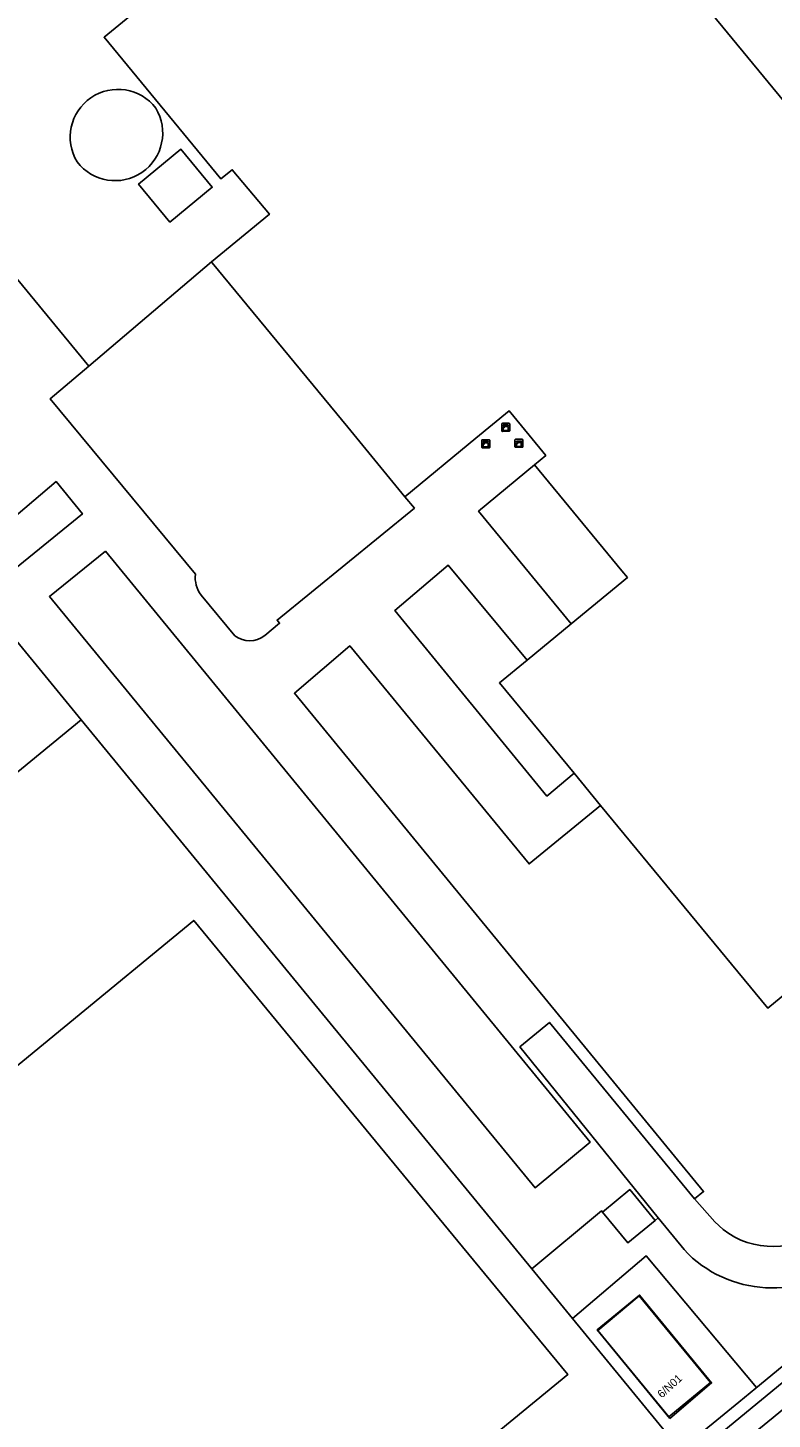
# Model space of a CAD drawing. Extents: x 156141 to 158132, y 385651 to 388333.
# Drawn here: x 157145.1 to 157238.1, y 386478.5 to 386652.3 of the extents above; entities that cross this region are included whole.
import ezdxf

# ---------------------------------------------------------------- set-up
doc = ezdxf.new("R2010")
doc.units = 0
for name, color, linetype in [('IMGEO_Berm_groen', 7, 'Continuous'), ('IMGEO_Erf', 7, 'Continuous'), ('IMGEO_Fietspad_gesloten', 7, 'Continuous'), ('IMGEO_Hek', 7, 'Continuous'), ('IMGEO_Kast', 7, 'Continuous'), ('IMGEO_Opslagtank', 7, 'Continuous'), ('IMGEO_Pand', 7, 'Continuous'), ('IMGEO_Pand_nummerreeks', 7, 'Continuous'), ('IMGEO_Pand_vergunning_verleend', 7, 'Continuous'), ('IMGEO_Parkeervlak_open', 7, 'Continuous'), ('IMGEO_Rijbaan_lokaal_gesloten', 7, 'Continuous'), ('IMGEO_Rijbaan_lokaal_open', 7, 'Continuous'), ('IMGEO_Voetpad_open', 7, 'Continuous')]:
    doc.layers.add(name, color=color, linetype=linetype)

msp = doc.modelspace()

# ---------------------------------------------------------------- linework, layer by layer
at = {"layer": 'IMGEO_Berm_groen'}
msp.add_lwpolyline([(157297.77, 386525.08), (157296.44, 386526.68), (157264.04, 386500), (157238.17, 386478.7), (157234.6, 386475.76), (157235.94, 386474.16), (157239.52, 386477.11), (157267.32, 386500)], close=True, dxfattribs=at)
at = {"layer": 'IMGEO_Erf'}
for points in [[(157186.93, 386707.01), (157239.52, 386643.16), (157264.92, 386664.1)], [(157114.64, 386656.27), (157152.67, 386610.07), (157167.99, 386623.07), (157175.23, 386629.04), (157170.59, 386634.6), (157169.18, 386633.44), (157154.59, 386651.15), (157160.34, 386655.89)], [(157227.04, 386499.66), (157223.8, 386503.61), (157223.42, 386503.29), (157220.03, 386500.5), (157216.85, 386504.35), (157216.73, 386504.5), (157208.03, 386497.24), (157213.1, 386491.07), (157226.61, 386474.61), (157226.82, 386474.79), (157233.89, 386480.6), (157236.03, 386482.36), (157257.45, 386500), (157293.78, 386529.91), (157370.16, 386592.8)], [(157226.61, 386474.61), (157213.1, 386491.07), (157208.03, 386497.24), (157151.72, 386565.87), (157139.12, 386581.23)], [(157282.73, 386567.14), (157237.49, 386529.84), (157216.6, 386555.17), (157207.68, 386547.85), (157185.27, 386575.09), (157178.36, 386569.18), (157229.49, 386506.92), (157228.35, 386505.99), (157230.88, 386503.14), (157231.91, 386502.18)]]:
    msp.add_lwpolyline(points, dxfattribs=at)
for points in [[(157168.09, 386632.41), (157162.8, 386628.06), (157158.89, 386632.81), (157164.19, 386637.16)], [(157116.21, 386500), (157127.1, 386508.96), (157133.36, 386514.12), (157165.78, 386540.8), (157199.38, 386500), (157212.51, 386484.05), (157183.01, 386459.8), (157181.86, 386461.2), (157166.86, 386448.84), (157138.86, 386425.77), (157126.75, 386415.79), (157110.04, 386436.12), (157108.67, 386434.94), (157079.79, 386470.01)], [(157230.33, 386483.05), (157225.14, 386478.78), (157216.28, 386489.57), (157221.44, 386493.87)]]:
    msp.add_lwpolyline(points, close=True, dxfattribs=at)
for centre, radius, start, end in [((157156.31, 386638.68), 5.96, 37.4168, 211.3385), ((157155.95, 386639.19), 5.96, 217.35, 31.4053), ((157238.09, 386510.07), 10.02, 231.9386, 310.0045), ((157238.01, 386509.86), 14.98, 222.9286, 311.103)]:
    msp.add_arc(centre, radius, start, end, dxfattribs=at)
at = {"layer": 'IMGEO_Fietspad_gesloten'}
for points in [[(157264.04, 386500), (157296.44, 386526.68), (157381.27, 386596.54), (157379.64, 386598.54), (157294.79, 386528.69), (157259.95, 386500), (157236.74, 386480.89), (157225.9, 386471.96), (157216.57, 386464.31), (157144.79, 386405.24)], [(157145.07, 386402.06), (157149.79, 386405.83), (157155.47, 386410.52), (157193.7, 386442.31), (157194.52, 386442.96), (157197.09, 386445.09), (157197.92, 386445.77), (157198.09, 386445.66), (157217.43, 386461.57), (157228.21, 386470.51), (157228.31, 386470.59), (157234.6, 386475.76), (157238.17, 386478.7), (157264.04, 386500)]]:
    msp.add_lwpolyline(points, dxfattribs=at)
at = {"layer": 'IMGEO_Hek'}
for points in [[(157151.72, 386565.87), (157049.18, 386481.68)], [(157213.1, 386491.07), (157222.33, 386498.88), (157236.11, 386482.43)]]:
    msp.add_lwpolyline(points, dxfattribs=at)
at = {"layer": 'IMGEO_Kast'}
for p, q in [((157204.26, 386601.98), (157204.26, 386602.82)), ((157204.26, 386602.82), (157204.26, 386601.98)), ((157204.34, 386602.91), (157205.18, 386602.91)), ((157205.18, 386602.91), (157204.34, 386602.91)), ((157205.19, 386601.91), (157204.35, 386601.91)), ((157204.35, 386601.91), (157205.19, 386601.91)), ((157205.26, 386602.83), (157205.26, 386601.99)), ((157205.26, 386601.99), (157205.26, 386602.83)), ((157201.76, 386599.93), (157201.76, 386600.77)), ((157201.76, 386600.77), (157201.76, 386599.93)), ((157201.84, 386600.85), (157202.68, 386600.85)), ((157202.68, 386600.85), (157201.84, 386600.85)), ((157202.76, 386600.78), (157202.76, 386599.94)), ((157202.76, 386599.94), (157202.76, 386600.78)), ((157205.91, 386599.98), (157205.91, 386600.82)), ((157205.91, 386600.82), (157205.91, 386599.98)), ((157205.99, 386600.91), (157206.83, 386600.91)), ((157206.83, 386600.91), (157205.99, 386600.91)), ((157206.91, 386600.83), (157206.91, 386599.99)), ((157206.91, 386599.99), (157206.91, 386600.83)), ((157202.69, 386599.86), (157201.85, 386599.86)), ((157201.85, 386599.86), (157202.69, 386599.86)), ((157206.84, 386599.91), (157206, 386599.91)), ((157206, 386599.91), (157206.84, 386599.91))]:
    msp.add_line(p, q, dxfattribs=at)
for points in [[(157204.46, 386602.7), (157205.06, 386602.7), (157205.06, 386602.61), (157204.46, 386602.61), (157204.46, 386602.7)], [(157204.46, 386602.52), (157205.06, 386602.52), (157205.06, 386602.03), (157204.46, 386602.03), (157204.46, 386602.52)], [(157201.96, 386600.65), (157202.56, 386600.65), (157202.56, 386600.56), (157201.96, 386600.56), (157201.96, 386600.65)], [(157201.96, 386600.47), (157202.56, 386600.47), (157202.56, 386599.98), (157201.96, 386599.98), (157201.96, 386600.47)], [(157206.11, 386600.7), (157206.71, 386600.7), (157206.71, 386600.61), (157206.11, 386600.61), (157206.11, 386600.7)], [(157206.11, 386600.52), (157206.71, 386600.52), (157206.71, 386600.03), (157206.11, 386600.03), (157206.11, 386600.52)]]:
    msp.add_lwpolyline(points, dxfattribs=at)
for centre in [(157204.54, 386602.37), (157202.04, 386600.32), (157206.19, 386600.37)]:
    msp.add_circle(centre, 0.0377, dxfattribs=at)
for centre, start, end in [((157204.34, 386602.83), 92.4484, 184.2845), ((157204.34, 386602.83), 92.4484, 184.2845), ((157204.34, 386601.98), 182.4484, 274.2845), ((157204.34, 386601.98), 182.4484, 274.2845), ((157205.18, 386602.83), 2.4484, 94.2845), ((157205.18, 386602.83), 2.4484, 94.2845), ((157205.18, 386601.98), 272.4484, 4.2845), ((157205.18, 386601.98), 272.4484, 4.2845), ((157201.84, 386600.78), 92.4484, 184.2845), ((157201.84, 386600.78), 92.4484, 184.2845), ((157201.84, 386599.93), 182.4484, 274.2845), ((157201.84, 386599.93), 182.4484, 274.2845), ((157202.69, 386600.78), 2.4484, 94.2845), ((157202.69, 386600.78), 2.4484, 94.2845), ((157202.69, 386599.93), 272.4484, 4.2845), ((157202.69, 386599.93), 272.4484, 4.2845), ((157205.99, 386600.83), 92.4484, 184.2845), ((157205.99, 386600.83), 92.4484, 184.2845), ((157205.99, 386599.99), 182.4484, 274.2845), ((157205.99, 386599.99), 182.4484, 274.2845), ((157206.83, 386600.83), 2.4484, 94.2845), ((157206.83, 386600.83), 2.4484, 94.2845), ((157206.83, 386599.99), 272.4484, 4.2845), ((157206.83, 386599.99), 272.4484, 4.2845)]:
    msp.add_arc(centre, 0.0779, start, end, dxfattribs=at)
at = {"layer": 'IMGEO_Opslagtank'}
for centre, start, end in [((157156.31, 386638.68), 37.4168, 211.3385), ((157155.95, 386639.19), 217.35, 31.4053)]:
    msp.add_arc(centre, 5.96, start, end, dxfattribs=at)
at = {"layer": 'IMGEO_Pand'}
for points in [[(157264.92, 386664.1), (157239.52, 386643.16), (157186.93, 386707.01)], [(157160.34, 386655.89), (157154.59, 386651.15), (157169.18, 386633.44), (157170.59, 386634.6), (157175.23, 386629.04), (157167.99, 386623.07), (157168.08, 386622.96), (157185.02, 386602.41), (157192.17, 386593.74), (157201.01, 386601.04), (157205.18, 386604.48), (157207.7, 386601.41), (157209.77, 386598.89), (157208.36, 386597.72), (157219.27, 386584.49), (157219.96, 386583.66), (157212.92, 386577.85), (157207.45, 386573.33), (157203.98, 386570.47), (157213.3, 386559.18), (157216.6, 386555.17), (157237.49, 386529.84), (157282.73, 386567.14)]]:
    msp.add_lwpolyline(points, dxfattribs=at)
for points in [[(157158.89, 386632.81), (157162.8, 386628.06), (157168.09, 386632.41), (157164.19, 386637.16)], [(157183.01, 386459.8), (157212.51, 386484.05), (157199.38, 386500), (157165.78, 386540.8), (157133.36, 386514.12), (157127.1, 386508.96), (157116.21, 386500), (157079.79, 386470.01), (157108.67, 386434.94), (157110.04, 386436.12), (157126.75, 386415.79), (157138.86, 386425.77), (157166.86, 386448.84), (157181.86, 386461.2)], [(157225.14, 386478.78), (157230.33, 386483.05), (157221.44, 386493.87), (157216.28, 386489.57)]]:
    msp.add_lwpolyline(points, close=True, dxfattribs=at)
at = {"layer": 'IMGEO_Pand_vergunning_verleend'}
msp.add_lwpolyline([(157225.26, 386478.56), (157216.19, 386489.64), (157221.49, 386493.98), (157230.48, 386483.01)], close=True, dxfattribs=at)
at = {"layer": 'IMGEO_Parkeervlak_open'}
for points in [[(157185.02, 386602.41), (157168.08, 386622.96), (157167.99, 386623.07), (157152.67, 386610.07), (157147.86, 386605.98), (157165.99, 386584.05)], [(157174.65, 386576.4), (157176.51, 386577.93), (157176.19, 386578.33), (157193.35, 386592.32), (157192.17, 386593.74), (157185.02, 386602.41)], [(157166.71, 386581.44), (157170.92, 386576.37)]]:
    msp.add_lwpolyline(points, dxfattribs=at)
for points in [[(157208.36, 386597.72), (157201.38, 386591.93), (157212.92, 386577.85), (157219.96, 386583.66), (157219.27, 386584.49)], [(157154.75, 386586.93), (157147.76, 386581.25), (157208.43, 386507.39), (157215.33, 386513.1)], [(157207.45, 386573.33), (157197.59, 386585.18), (157190.91, 386579.53), (157209.92, 386556.34), (157213.3, 386559.18), (157203.98, 386570.47)], [(157216.85, 386504.35), (157220.03, 386500.5), (157223.42, 386503.29), (157220.26, 386507.15)]]:
    msp.add_lwpolyline(points, close=True, dxfattribs=at)
for centre, radius, start, end in [((157169.6, 386583.65), 3.63, 173.6566, 217.4798), ((157172.77, 386578.72), 2.99, 231.8148, 309.0463)]:
    msp.add_arc(centre, radius, start, end, dxfattribs=at)
at = {"layer": 'IMGEO_Rijbaan_lokaal_gesloten'}
msp.add_lwpolyline([(157231.91, 386502.18), (157230.88, 386503.14), (157228.35, 386505.99), (157210.23, 386528.05), (157206.54, 386524.99), (157223.8, 386503.61), (157227.04, 386499.66)], dxfattribs=at)
for centre, radius, start, end in [((157238.09, 386510.07), 10.02, 231.9386, 310.0045), ((157238.01, 386509.86), 14.98, 222.9286, 311.103)]:
    msp.add_arc(centre, radius, start, end, dxfattribs=at)
at = {"layer": 'IMGEO_Rijbaan_lokaal_open'}
for points in [[(157165.99, 386584.05), (157147.86, 386605.98), (157152.67, 386610.07), (157114.64, 386656.27), (157186.27, 386715.37)], [(157135.98, 386584.94), (157148.59, 386595.62), (157151.87, 386591.58), (157139.12, 386581.23), (157151.72, 386565.87), (157208.03, 386497.24), (157216.73, 386504.5), (157216.85, 386504.35), (157220.26, 386507.15), (157223.42, 386503.29), (157223.8, 386503.61), (157206.54, 386524.99), (157210.23, 386528.05), (157228.35, 386505.99), (157229.49, 386506.92), (157178.36, 386569.18), (157185.27, 386575.09), (157207.68, 386547.85), (157216.6, 386555.17), (157213.3, 386559.18), (157209.92, 386556.34), (157190.91, 386579.53), (157197.59, 386585.18), (157207.45, 386573.33), (157212.92, 386577.85), (157201.38, 386591.93), (157208.36, 386597.72), (157209.77, 386598.89), (157207.7, 386601.41), (157205.18, 386604.48), (157201.01, 386601.04), (157192.17, 386593.74), (157193.35, 386592.32), (157176.19, 386578.33), (157176.51, 386577.93), (157174.65, 386576.4)], [(157170.92, 386576.37), (157166.71, 386581.44)]]:
    msp.add_lwpolyline(points, dxfattribs=at)
msp.add_lwpolyline([(157154.75, 386586.93), (157215.33, 386513.1), (157208.43, 386507.39), (157147.76, 386581.25)], close=True, dxfattribs=at)
for centre, radius, start, end in [((157169.6, 386583.65), 3.63, 173.6566, 217.4798), ((157172.77, 386578.72), 2.99, 231.8148, 309.0463)]:
    msp.add_arc(centre, radius, start, end, dxfattribs=at)
at = {"layer": 'IMGEO_Voetpad_open'}
for points in [[(157379.64, 386598.54), (157378.62, 386599.78), (157370.16, 386592.8), (157293.78, 386529.91), (157257.45, 386500), (157236.03, 386482.36), (157233.89, 386480.6), (157226.82, 386474.79), (157226.61, 386474.61), (157224.92, 386473.22), (157225.9, 386471.96), (157236.74, 386480.89), (157259.95, 386500), (157294.79, 386528.69)], [(157151.87, 386591.58), (157148.59, 386595.62), (157135.98, 386584.94), (157132.44, 386581.94), (157135.47, 386578.26), (157139.12, 386581.23)]]:
    msp.add_lwpolyline(points, close=True, dxfattribs=at)

# ---------------------------------------------------------------- texts
at = {"layer": 'IMGEO_Pand_nummerreeks'}
msp.add_text('6/N01', height=1, rotation=42.337, dxfattribs=at).set_placement((157224.27, 386481.04))

doc.saveas('drawing.dxf')
